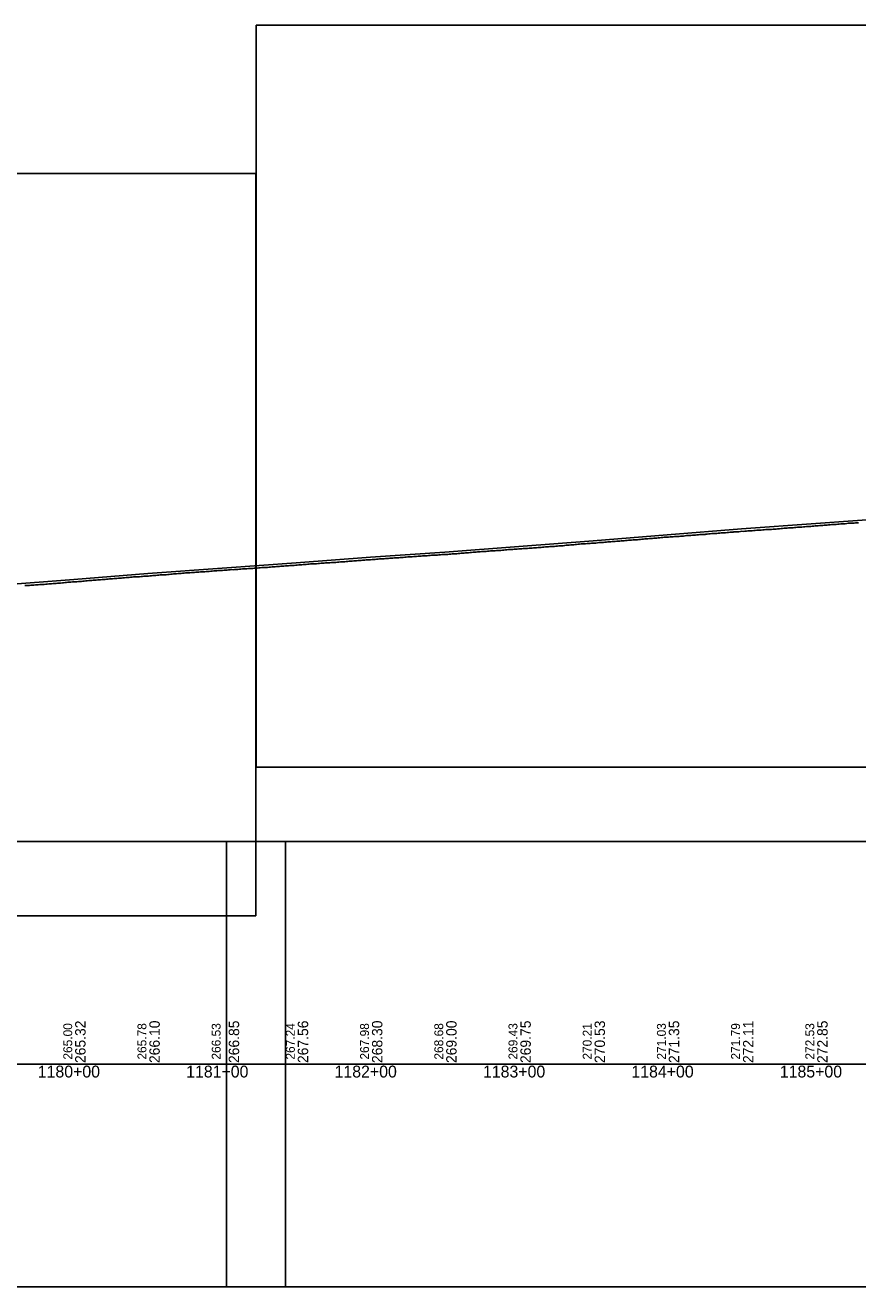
# Model space of a CAD drawing. Extents: x -3627 to 47473, y 2850 to 4350.
# Drawn here: x 5345 to 5906, y 2850 to 3700 of the extents above; entities that cross this region are included whole.
import ezdxf

# ---------------------------------------------------------------- set-up
doc = ezdxf.new("R2010")
doc.units = 0
for name, color, linetype in [('RD_DDB_Profile_EX', 7, 'Continuous'), ('RD_DDB_Profile_PR', 7, 'Continuous'), ('RD_DDB_StaTX', 7, 'Continuous'), ('RD_DDB_StripGrade', 7, 'Continuous'), ('RD_GPK_Profile_Cell', 7, 'Continuous'), ('RD_SHT_ShtClip', 7, 'Continuous')]:
    doc.layers.add(name, color=color, linetype=linetype)

msp = doc.modelspace()

# ---------------------------------------------------------------- linework, layer by layer
at = {"layer": 'RD_DDB_Profile_EX'}
for points in [[(5798.229977, 3356.69867), (5799.222682, 3356.79824), (5800.225608, 3356.898635), (5801.228551, 3356.89915), (5802.221487, 3356.89971), (5802.92116, 3356.96976), (5803.224607, 3356.99988), (5804.228141, 3357.199425), (5805.221768, 3357.248965), (5806.225307, 3357.34847), (5807.228825, 3357.44803), (5808.222465, 3357.447745), (5809.22334, 3357.497215), (5809.60623, 3357.54709), (5810.608419, 3357.59767), (5811.610011, 3357.69792), (5812.613259, 3357.847365), (5813.60566, 3357.89789), (5814.608023, 3357.948375), (5815.610385, 3358.04886), (5816.603687, 3358.098425), (5817.606034, 3358.198835), (5818.608396, 3358.29932), (5819.610758, 3358.399795), (5820.076393, 3358.42346), (5820.603233, 3358.44975), (5821.104097, 3358.474965), (5821.606407, 3358.49979), (5822.063239, 3358.568365), (5822.608856, 3358.6497), (5823.601401, 3358.69923), (5824.60393, 3358.698795), (5825.60702, 3358.74925), (5826.59957, 3358.898715), (5827.602099, 3358.998165), (5828.604607, 3358.997815), (5829.607709, 3359.098115), (5830.600267, 3359.197745), (5831.602797, 3359.24722), (5832.605297, 3359.346555), (5833.59787, 3359.346575), (5834.600738, 3359.347295), (5835.603233, 3359.49637), (5836.60569, 3359.59606), (5837.598242, 3359.69545), (5838.601372, 3359.745905), (5839.603826, 3359.795405), (5840.596383, 3359.894525), (5841.59888, 3359.993735), (5842.601323, 3360.09345), (5843.604455, 3360.143945), (5844.597023, 3360.144025), (5845.599462, 3360.19383), (5846.601957, 3360.29304), (5847.595167, 3360.343565), (5848.597603, 3360.393705), (5849.600098, 3360.443595), (5850.602589, 3360.542805), (5851.595105, 3360.69167), (5852.020813, 3360.69349), (5853.023705, 3360.79356), (5854.016442, 3360.89318), (5855.019334, 3360.94359), (5856.022226, 3361.0437), (5857.025062, 3361.14385), (5858.017992, 3361.194375), (5859.020884, 3361.24553), (5860.023587, 3361.295105), (5861.016512, 3361.39509), (5862.019404, 3361.445735), (5863.022257, 3361.546145), (5864.01517, 3361.64645), (5865.018062, 3361.69688), (5866.020782, 3361.696925), (5867.01369, 3361.74735), (5868.016557, 3361.84759), (5869.019453, 3361.947875), (5870.022349, 3362.098115), (5871.015228, 3362.14876), (5872.017977, 3362.19831), (5873.020873, 3362.248785), (5874.013752, 3362.349235), (5875.016648, 3362.449625), (5876.019564, 3362.549985), (5877.012761, 3362.599425), (5878.015233, 3362.74996), (5879.018813, 3362.74952), (5880.012492, 3362.898915), (5881.016075, 3362.898565), (5882.019639, 3362.948125), (5883.01333, 3363.047615), (5884.014334, 3363.146915), (5885.018887, 3363.197445), (5886.022462, 3363.346965), (5887.01616, 3363.44641), (5888.019703, 3363.49576), (5889.023281, 3363.54526), (5890.012721, 3363.54468), (5891.018987, 3363.69542), (5892.213059, 3363.794135), (5893.205271, 3363.844385)], [(5893.205271, 3363.844385), (5894.208776, 3363.943865), (5895.210814, 3363.99508), (5896.20444, 3364.044545), (5897.206521, 3364.14527), (5898.209979, 3364.29412), (5899.202185, 3364.394375), (5900.20569, 3364.39409), (5901.207728, 3364.444855), (5902.211236, 3364.544605), (5903.204816, 3364.59433), (5904.206906, 3364.744575), (5905.210409, 3364.79411), (5906.202584, 3364.794775)], [(5698.226306, 3348.73406), (5699.229072, 3348.78362), (5700.231841, 3348.8832), (5701.224587, 3348.884635), (5702.227356, 3348.935185), (5703.230122, 3349.03292), (5704.232696, 3349.131555), (5705.225638, 3349.23217), (5706.228407, 3349.281775), (5707.231086, 3349.332135), (5708.23385, 3349.52971), (5709.2268, 3349.62932), (5710.229569, 3349.727825), (5711.23212, 3349.777345), (5712.234885, 3349.82909), (5713.227852, 3349.829835), (5714.230392, 3349.879445), (5715.233155, 3350.074375), (5716.236039, 3350.225975), (5717.228782, 3350.32673), (5718.231547, 3350.42392), (5719.234312, 3350.473445), (5720.237074, 3350.475405), (5721.229821, 3350.525035), (5722.232583, 3350.67204), (5723.235348, 3350.722855), (5724.237847, 3350.723695), (5725.230976, 3350.775465), (5726.233738, 3350.972405), (5727.236236, 3351.021955), (5728.229247, 3351.12019), (5729.232013, 3351.07247), (5730.234775, 3351.170615), (5731.237257, 3351.367325), (5732.230285, 3351.466875), (5733.252636, 3351.51863), (5734.255242, 3351.56906), (5735.248399, 3351.670965), (5736.251287, 3351.770015), (5737.253911, 3351.869125), (5738.247051, 3351.92097), (5739.249943, 3351.971425), (5740.240013, 3352.070595), (5741.233379, 3352.1224), (5742.236228, 3352.17409), (5743.239328, 3352.27331), (5744.232667, 3352.32381), (5745.23553, 3352.4731), (5746.23863, 3352.52702), (5747.23197, 3352.578625), (5748.234845, 3352.627915), (5749.237945, 3352.87508), (5750.231272, 3352.92563), (5751.234161, 3352.976105), (5752.237261, 3353.0276), (5753.230575, 3353.078125), (5754.233476, 3353.178585), (5755.236576, 3353.278085), (5756.229866, 3353.330475), (5757.232781, 3353.33182), (5758.235882, 3353.43135), (5759.22917, 3353.580985), (5760.232097, 3353.682285), (5761.235198, 3353.78272), (5762.228473, 3353.834025), (5763.231414, 3353.93366), (5764.234514, 3354.03334), (5765.227218, 3354.08215), (5766.230163, 3354.084135), (5767.233263, 3354.23457), (5768.226512, 3354.383635), (5769.229471, 3354.434115), (5770.232571, 3354.48526), (5771.225816, 3354.53708), (5772.228912, 3354.68562), (5773.231887, 3354.83428), (5774.225119, 3354.885485), (5775.228215, 3354.988245), (5776.231204, 3355.03868), (5777.224422, 3355.137635), (5778.227518, 3355.137145), (5779.230514, 3355.19052), (5780.22372, 3355.33965), (5781.226817, 3355.390555), (5782.229831, 3355.44142), (5783.223024, 3355.44269), (5784.226121, 3355.493085), (5785.229148, 3355.59348), (5786.222328, 3355.643615), (5787.225424, 3355.843435), (5788.228465, 3355.844725), (5789.221632, 3355.89518), (5790.224728, 3356.094645), (5791.22778, 3356.145115), (5792.220934, 3356.19567), (5793.22403, 3356.246315), (5794.227098, 3356.39677), (5795.230199, 3356.447225), (5796.223335, 3356.49786), (5797.227035, 3356.598375), (5798.229977, 3356.69867)], [(5499.018161, 3334.180605), (5500.011169, 3334.182955), (5501.014176, 3334.234235), (5502.01719, 3334.333675), (5503.009996, 3334.3824), (5504.012818, 3334.53187), (5505.015826, 3334.582265), (5506.008627, 3334.53369), (5507.011461, 3334.732285), (5508.014469, 3334.734415), (5509.017088, 3334.83223), (5510.01027, 3334.931825), (5511.013112, 3334.9831), (5512.015731, 3335.034385), (5513.00891, 3335.0848), (5514.01175, 3335.233505), (5515.014368, 3335.283055), (5516.00755, 3335.382705), (5517.010555, 3335.483925), (5518.013012, 3335.533475), (5519.016021, 3335.633065), (5520.009195, 3335.684345), (5521.011817, 3335.6847), (5522.014666, 3335.832725), (5523.00783, 3335.88247), (5524.010452, 3335.88352), (5525.013311, 3335.93548), (5526.006471, 3336.03518), (5527.009093, 3336.183965), (5528.012099, 3336.23438), (5529.005113, 3336.334885), (5530.008119, 3336.435305), (5531.010741, 3336.534105), (5532.013607, 3336.63314), (5533.006756, 3336.63506), (5534.009383, 3336.635975), (5535.01239, 3336.785695), (5536.005399, 3336.88553), (5537.00802, 3337.03435), (5538.011033, 3337.134825), (5539.004169, 3337.18536), (5540.006663, 3337.18484), (5541.009671, 3337.18594), (5542.012679, 3337.237005), (5543.005306, 3337.38533), (5544.008314, 3337.486415), (5545.009885, 3337.43805), (5546.002589, 3337.537055), (5547.005523, 3337.686885), (5548.008586, 3337.73734), (5549.00128, 3337.78691), (5550.004339, 3337.837365), (5551.007283, 3337.93837), (5551.999971, 3337.98853), (5553.003031, 3338.08784), (5554.005979, 3338.089885), (5555.009043, 3338.18977), (5556.001723, 3338.288845), (5557.004681, 3338.339285), (5558.00774, 3338.3902), (5559.000416, 3338.53879), (5560.003476, 3338.540225), (5561.006438, 3338.59157), (5561.999114, 3338.73976), (5563.002169, 3338.79066), (5564.005141, 3338.84152), (5565.007705, 3338.941085), (5566.000868, 3339.0411), (5567.003924, 3339.141085), (5568.006403, 3339.14105), (5568.999562, 3339.241535), (5570.002618, 3339.34154), (5571.005106, 3339.39107), (5571.998256, 3339.491565), (5573.001317, 3339.591625), (5573.436886, 3339.59218), (5574.429679, 3339.74229), (5575.43251, 3339.792205), (5576.435332, 3339.793355), (5577.428134, 3339.892615), (5578.430956, 3339.99227), (5579.433778, 3340.043055), (5580.42658, 3340.093395), (5581.429402, 3340.24308), (5582.432232, 3340.29262), (5583.435054, 3340.393035), (5584.427847, 3340.44352), (5585.430678, 3340.49306), (5586.4335, 3340.54413), (5587.426293, 3340.594865), (5588.429124, 3340.693825), (5589.431946, 3340.79422), (5590.424813, 3340.843845), (5591.42757, 3340.944245), (5592.430392, 3340.99492), (5593.423254, 3341.044265), (5594.426015, 3341.09466), (5595.428846, 3341.24362), (5596.431668, 3341.244905), (5597.424513, 3341.2956), (5598.427292, 3341.29521)], [(5598.427292, 3341.29521), (5599.430114, 3341.34582), (5600.422954, 3341.495735), (5601.425738, 3341.6448), (5602.42856, 3341.74546), (5603.421413, 3341.745345), (5604.424231, 3341.79572), (5605.427005, 3341.89588), (5606.419855, 3341.94574), (5607.422672, 3341.99612), (5608.42546, 3342.095225), (5609.428282, 3342.195645), (5610.421036, 3342.24613), (5611.423819, 3342.345665), (5612.426649, 3342.396285), (5613.419486, 3342.49657), (5614.422312, 3342.546305), (5615.425104, 3342.596875), (5616.417937, 3342.74594), (5617.420763, 3342.79638), (5618.423558, 3342.89682), (5619.416387, 3342.946575), (5620.419213, 3342.947295), (5621.422039, 3342.99688), (5622.424835, 3343.04726), (5623.417663, 3343.097695), (5624.420489, 3343.19713), (5625.423289, 3343.297655), (5626.416113, 3343.2973), (5627.418939, 3343.39768), (5628.421766, 3343.398275), (5629.414563, 3343.497955), (5630.41739, 3343.59808), (5631.420216, 3343.648545), (5632.42302, 3343.74815), (5633.41584, 3343.84848), (5634.418666, 3343.84828), (5635.421492, 3343.948445), (5636.41429, 3344.04882), (5637.417116, 3344.148465), (5638.419942, 3344.24878), (5639.41274, 3344.29857), (5640.415566, 3344.34887), (5641.418392, 3344.44925), (5642.411203, 3344.548825), (5643.414016, 3344.59923), (5644.416843, 3344.74961), (5645.419669, 3344.74919), (5646.412467, 3344.849655), (5647.415293, 3344.899215), (5648.418119, 3344.999635), (5649.482507, 3345.104405), (5650.223375, 3345.149115), (5651.214973, 3345.19865), (5652.219003, 3345.299225), (5653.221922, 3345.348805), (5654.223044, 3345.44821), (5655.217719, 3345.49814), (5656.220639, 3345.64748), (5657.220431, 3345.69688), (5658.226441, 3345.79642), (5659.219355, 3345.84642), (5660.217819, 3345.89578), (5661.224975, 3345.89638), (5662.213463, 3345.995585), (5663.220812, 3346.09561), (5664.223677, 3346.19519), (5665.22077, 3346.194775), (5666.219527, 3346.29473), (5667.222446, 3346.394335), (5668.218219, 3346.49323), (5669.220603, 3346.59242), (5670.218776, 3346.69361), (5671.221476, 3346.7432), (5672.224246, 3346.74278), (5673.227018, 3346.792795), (5674.219768, 3346.942015), (5675.222539, 3347.04114), (5676.22531, 3347.0907), (5677.227979, 3347.14027), (5678.220832, 3347.23936), (5679.223603, 3347.239465), (5680.226479, 3347.340385), (5681.229139, 3347.39054), (5682.222001, 3347.4402), (5683.224773, 3347.53922), (5684.227419, 3347.589425), (5685.230186, 3347.63969), (5686.223066, 3347.738045), (5687.225701, 3347.83764), (5688.228468, 3347.887235), (5689.231347, 3347.987605), (5690.224237, 3348.08655), (5691.226862, 3348.185385), (5692.22963, 3348.18569), (5693.232396, 3348.33603), (5694.225144, 3348.386485), (5695.227911, 3348.484455), (5696.230679, 3348.534035), (5697.223425, 3348.63452), (5698.226306, 3348.73406)], [(5399.49614, 3326.695295), (5400.498925, 3326.74545), (5401.50171, 3326.894475), (5402.494551, 3327.044335), (5403.497336, 3327.09388), (5404.500121, 3327.143755), (5405.502923, 3327.194455), (5406.495747, 3327.2441), (5407.498532, 3327.34299), (5408.501317, 3327.44291), (5409.494158, 3327.54336), (5410.496943, 3327.5933), (5411.499729, 3327.7425), (5412.701449, 3327.842075), (5413.704137, 3327.89162), (5414.707089, 3327.992435), (5415.709777, 3328.042), (5416.702457, 3328.190745), (5417.705406, 3328.290755), (5418.703124, 3328.34026), (5419.695683, 3328.3403), (5420.707625, 3328.392495), (5421.701208, 3328.44165), (5422.693772, 3328.5413), (5423.696115, 3328.640395), (5424.709022, 3328.74031), (5425.70174, 3328.83884), (5426.694314, 3328.889475), (5427.707532, 3328.8914), (5428.699826, 3328.98996), (5429.692404, 3329.090145), (5430.70604, 3329.14105), (5431.708929, 3329.240675), (5432.700363, 3329.28972), (5433.70467, 3329.389965), (5434.707438, 3329.539745), (5435.698451, 3329.58875), (5436.690922, 3329.58839), (5437.694105, 3329.73819), (5438.696549, 3329.739585), (5439.698867, 3329.74048), (5440.692194, 3329.889605), (5441.694638, 3329.9886), (5442.696953, 3330.137545), (5443.689557, 3330.18786), (5444.692739, 3330.33758), (5445.708604, 3330.437155), (5446.697482, 3330.43673), (5447.69083, 3330.537185), (5448.693277, 3330.63607), (5449.695581, 3330.68563), (5450.6882, 3330.735255), (5451.69138, 3330.786385), (5452.708494, 3330.93744), (5453.696114, 3330.9863), (5454.689473, 3330.987465), (5455.706997, 3331.13786), (5456.694216, 3331.28516), (5457.687578, 3331.336365), (5458.7055, 3331.33753), (5459.692307, 3331.43557), (5460.684945, 3331.486055), (5461.687964, 3331.488005), (5462.690411, 3331.685215), (5463.692859, 3331.78314), (5464.702506, 3331.78524), (5465.688504, 3331.784845), (5466.690952, 3331.88359), (5467.684329, 3331.9832), (5468.68661, 3331.98449), (5469.689059, 3332.084985), (5470.691509, 3332.23281), (5471.702394, 3332.332365), (5472.687154, 3332.33193), (5473.689605, 3332.481495), (5474.682813, 3332.531065), (5475.685263, 3332.581535), (5476.701544, 3332.632045), (5477.704239, 3332.682415), (5478.697169, 3332.83111), (5479.699935, 3332.78261), (5480.702699, 3332.88122), (5481.69556, 3332.980685), (5482.698324, 3333.13024), (5483.70109, 3333.17981), (5484.703772, 3333.13218), (5485.696715, 3333.280825), (5486.699478, 3333.37937), (5487.702359, 3333.380775), (5488.016611, 3333.38045), (5489.019423, 3333.431845), (5490.012247, 3333.579445), (5491.015252, 3333.727815), (5492.018258, 3333.729235), (5493.010887, 3333.77986), (5494.013893, 3333.830245), (5495.016899, 3333.93064), (5496.019321, 3334.03019), (5497.012527, 3334.031615), (5498.015541, 3334.032), (5499.018161, 3334.180605)], [(5344.496929, 3322.39454), (5345.499221, 3322.544615), (5346.50249, 3322.54435), (5347.50483, 3322.594875), (5348.497211, 3322.69552), (5349.499551, 3322.69637), (5350.50282, 3322.74595), (5351.495236, 3322.84617), (5352.497541, 3322.89665), (5353.50081, 3322.99621), (5354.50315, 3323.14639), (5355.495532, 3323.19684), (5356.497873, 3323.247475), (5357.50114, 3323.247145), (5358.493544, 3323.34745), (5359.495862, 3323.497595), (5360.49913, 3323.597385), (5361.50147, 3323.64791), (5362.493865, 3323.69829), (5363.496193, 3323.748785), (5364.49946, 3323.84847), (5365.5018, 3323.89893), (5366.494182, 3324.0493), (5367.497451, 3324.14899), (5368.499791, 3324.14947), (5369.735653, 3324.32429), (5370.494849, 3324.39967), (5371.651321, 3324.472975), (5372.500497, 3324.59961), (5373.49326, 3324.74914), (5374.496124, 3324.79962), (5375.498908, 3324.84918), (5376.501693, 3324.898785), (5377.494535, 3324.999205), (5378.497319, 3324.99887), (5379.500104, 3325.048545), (5380.554565, 3325.147395), (5381.531356, 3325.197205), (5382.52588, 3325.294685), (5383.512913, 3325.342505), (5384.486257, 3325.44212), (5385.466107, 3325.538335), (5386.438604, 3325.682585), (5387.492474, 3325.79657), (5388.495337, 3325.79714), (5389.498122, 3325.8967), (5390.500907, 3326.046265), (5391.493749, 3326.0969), (5392.496533, 3326.146485), (5393.499318, 3326.246075), (5394.502103, 3326.2959), (5395.494944, 3326.396095), (5396.497729, 3326.495445), (5397.500514, 3326.54501), (5398.493356, 3326.645465), (5399.49614, 3326.695295)]]:
    msp.add_lwpolyline(points, dxfattribs=at)
at = {"layer": 'RD_DDB_Profile_PR'}
msp.add_lwpolyline([(5327.33, 3322.6905), (5377.33, 3326.5825), (5427.33, 3330.4905), (5477.33, 3334.2635), (5527.33, 3337.8), (5577.33, 3341.483), (5627.33, 3344.989), (5677.33, 3348.7505), (5727.33, 3352.631), (5777.33, 3356.7375), (5827.33, 3360.571), (5877.33, 3364.247), (5927.33, 3367.962), (5977.33, 3372.152), (6027.33, 3376.6585), (6077.33, 3381.2475), (6127.33, 3386.648), (6177.33, 3392.4305), (6227.33, 3398.0855), (6277.33, 3404.256), (6327.33, 3410.802), (6377.33, 3417.8195), (6427.33, 3425.168), (6477.33, 3432.897)], dxfattribs=at)
at = {"layer": 'RD_GPK_Profile_Cell'}
msp.add_line((1000, 3000), (46705.077602, 3000), dxfattribs=at)
at = {"layer": 'RD_SHT_ShtClip'}
for points in [[(7000.165, 3200), (7000.165, 3700), (7000.165, 3700), (5500.33, 3700), (5500.33, 3200)], [(5500.165, 3100), (5500.165, 3600), (5500.165, 3600), (4000.33, 3600), (4000.33, 3100)], [(3980.33, 3150), (5520, 3150), (5520, 2850), (3980.33, 2850)], [(5480.33, 3150), (7020, 3150), (7020, 2850), (5480.33, 2850)]]:
    msp.add_lwpolyline(points, close=True, dxfattribs=at)

# ---------------------------------------------------------------- texts
at = {"layer": 'RD_DDB_StaTX'}
for s, p in [('1180+00', (5353.125471, 2991)), ('1181+00', (5453.125471, 2991)), ('1182+00', (5553.125471, 2991)), ('1183+00', (5653.125471, 2991)), ('1184+00', (5753.125471, 2991)), ('1185+00', (5853.125471, 2991))]:
    msp.add_text(s, height=8, dxfattribs=at).set_placement(p)
at = {"layer": 'RD_DDB_StripGrade'}
for s, height, p in [('265.00', 6, (5376.33, 3003.073688)), ('265.32', 7, (5385.33, 3000.75)), ('265.78', 6, (5426.33, 3003.073688)), ('266.10', 7, (5435.33, 3000.75)), ('266.53', 6, (5476.33, 3003.073688)), ('266.85', 7, (5488.83, 3000.75)), ('267.24', 6, (5526.33, 3003.073688)), ('267.56', 7, (5535.33, 3000.75)), ('267.98', 6, (5576.33, 3003.073688)), ('268.30', 7, (5585.33, 3000.75)), ('268.68', 6, (5626.33, 3003.073688)), ('269.00', 7, (5635.33, 3000.75)), ('269.43', 6, (5676.33, 3003.073688)), ('269.75', 7, (5685.33, 3000.75)), ('270.21', 6, (5726.33, 3003.073688)), ('270.53', 7, (5735.33, 3000.75)), ('271.03', 6, (5776.33, 3003.073688)), ('271.35', 7, (5785.33, 3000.75)), ('271.79', 6, (5826.33, 3003.073688)), ('272.11', 7, (5835.33, 3000.75)), ('272.53', 6, (5876.33, 3003.073688)), ('272.85', 7, (5885.33, 3000.75))]:
    msp.add_text(s, height=height, rotation=90, dxfattribs=at).set_placement(p)

doc.saveas('drawing.dxf')
